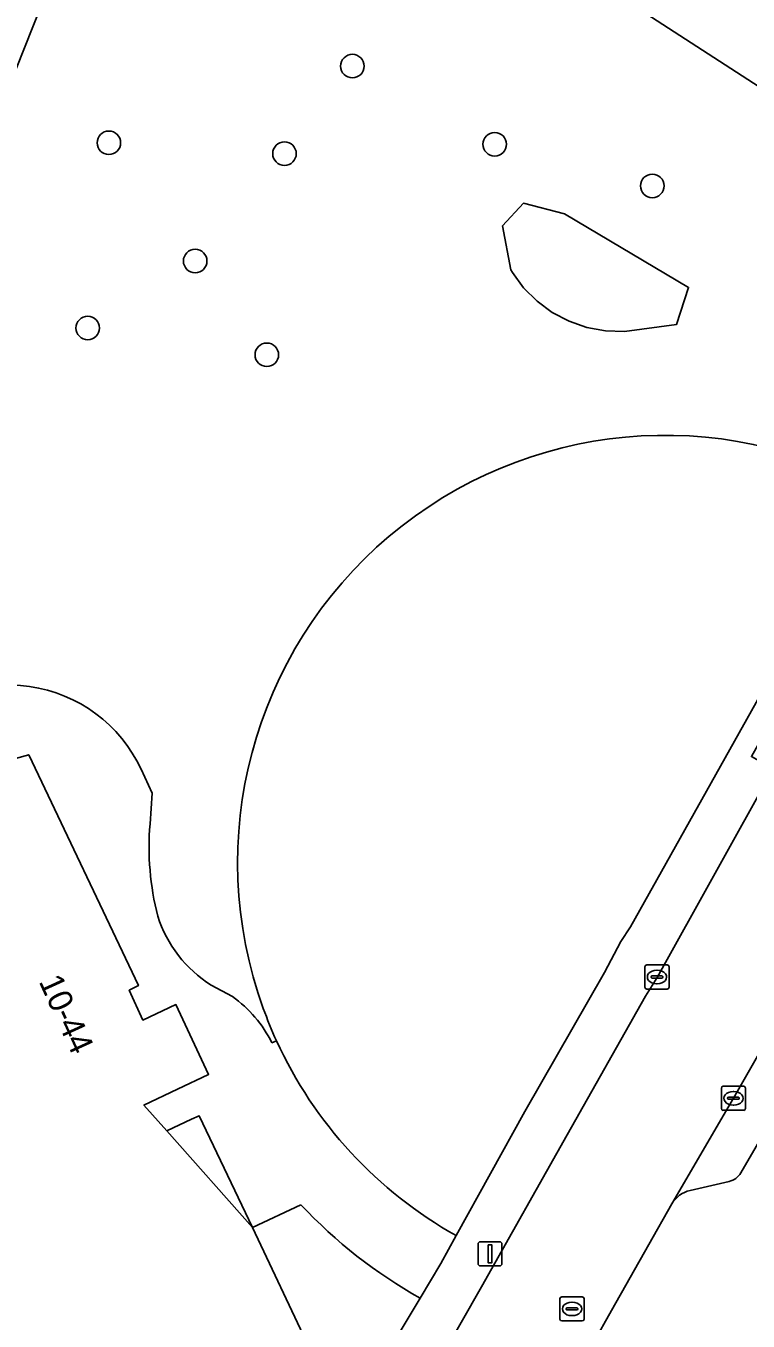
# Model space of a CAD drawing. Extents: x 159039 to 160102, y 381214 to 382524.
# Drawn here: x 159155.6 to 159185.6, y 381504.4 to 381558.2 of the extents above; entities that cross this region are included whole.
import ezdxf

# ---------------------------------------------------------------- set-up
doc = ezdxf.new("R2010")
doc.units = 0
for name, color, linetype in [('IMGEO_Boom', 7, 'Continuous'), ('IMGEO_Erf', 7, 'Continuous'), ('IMGEO_Groenvoorziening', 7, 'Continuous'), ('IMGEO_Kolk', 7, 'Continuous'), ('IMGEO_Lichtmast', 7, 'Continuous'), ('IMGEO_Pand', 7, 'Continuous'), ('IMGEO_Pand_nummerreeks', 7, 'Continuous'), ('IMGEO_Pand_overbouw', 7, 'Continuous'), ('IMGEO_Parkeervlak_open', 7, 'Continuous'), ('IMGEO_Rijbaan_lokaal_open', 7, 'Continuous'), ('IMGEO_Rioolput', 7, 'Continuous'), ('IMGEO_Voetpad_gesloten', 7, 'Continuous'), ('IMGEO_Voetpad_open', 7, 'Continuous')]:
    doc.layers.add(name, color=color, linetype=linetype)

msp = doc.modelspace()

# ---------------------------------------------------------------- linework, layer by layer
at = {"layer": 'IMGEO_Boom'}
for centre in [(159169.139, 381556.534), (159159.027, 381553.349), (159175.05, 381553.286), (159166.319, 381552.897), (159181.596, 381551.557), (159162.611, 381548.437), (159158.149, 381545.655), (159165.585, 381544.543)]:
    msp.add_circle(centre, 0.489, dxfattribs=at)
at = {"layer": 'IMGEO_Erf'}
msp.add_lwpolyline([(159173.453, 381507.955), (159176.296, 381513.115), (159179.604, 381518.88), (159180.292, 381520.169), (159180.696, 381520.785), (159188.162, 381534.124)], dxfattribs=at)
for centre, radius, start, end in [((159182.126, 381523.448), 17.751, 60.4649, 199.9506), ((159181.798, 381523.28), 17.386, 199.8006, 204.5674), ((159182.077, 381523.4), 17.69, 204.5429, 240.8212)]:
    msp.add_arc(centre, radius, start, end, dxfattribs=at)
at = {"layer": 'IMGEO_Groenvoorziening'}
for points in [[(159158.057, 381563.692), (159161.808, 381573.142), (159161.508, 381573.461), (159160.293, 381571.457), (159154.085, 381561.22), (159151.173, 381556.012), (159148.566, 381551.33), (159146.166, 381545.626), (159145.339, 381543.436), (159140.045, 381530.62), (159140.868, 381529.336), (159136.478, 381523.278), (159130.325, 381507.666), (159131.192, 381507.27), (159125.637, 381493.475), (159122.953, 381486.796), (159119.27, 381477.62), (159113.09, 381463.075), (159114.042, 381461.53), (159112.591, 381458.378), (159111.373, 381458.253), (159110.752, 381456.84), (159114.684, 381454.43)], [(159182.596, 381545.796), (159183.105, 381547.338), (159177.943, 381550.401), (159176.249, 381550.834), (159175.369, 381549.898), (159175.72, 381548.077), (159175.788, 381547.964), (159176.252, 381547.327), (159176.807, 381546.768), (159177.44, 381546.3), (159178.138, 381545.933), (159178.882, 381545.676), (159179.657, 381545.535), (159180.445, 381545.513)], [(159176.807, 381546.768), (159176.252, 381547.327), (159175.788, 381547.964), (159175.72, 381548.077), (159175.369, 381549.898), (159176.249, 381550.834), (159177.943, 381550.401), (159183.105, 381547.338), (159182.596, 381545.796), (159180.445, 381545.513), (159179.657, 381545.535), (159178.882, 381545.676), (159178.138, 381545.933), (159177.44, 381546.3)]]:
    msp.add_lwpolyline(points, close=True, dxfattribs=at)
for points in [[(159161.808, 381573.142), (159158.057, 381563.692), (159114.684, 381454.43), (159135.156, 381441.882)], [(159190.876, 381538.892), (159196.616, 381548.975), (159187.447, 381554.752), (159174.078, 381563.426), (159170.192, 381566.118)], [(159160.362, 381527.332), (159160.828, 381526.333), (159160.778, 381525.693), (159160.735, 381525.054)], [(159163.28, 381518.359), (159164.161, 381517.882)], [(159165.798, 381515.968), (159165.986, 381516.052)], [(159167, 381509.238), (159164.998, 381508.293), (159167.335, 381503.341), (159162.596, 381500), (159160.539, 381498.55), (159160.457, 381498.721), (159159.843, 381500), (159159.098, 381501.553), (159156.827, 381500.943), (159153.317, 381500)], [(159155.446, 381476.063), (159157.2, 381479.172), (159168.747, 381500), (159171.954, 381505.356)]]:
    msp.add_lwpolyline(points, dxfattribs=at)
for centre, radius, start, end in [((159182.126, 381523.448), 17.751, 60.4649, 199.9506), ((159154.882, 381524.776), 6.047, 25.0035, 138.8275), ((159172.244, 381524.098), 11.549, 175.2532, 194.3758), ((159166.045, 381522.795), 5.227, 197.412, 238.0695), ((159161.022, 381513.541), 5.357, 26.9441, 54.1352), ((159181.798, 381523.28), 17.386, 199.8006, 204.5674), ((159182.126, 381523.438), 20.747, 223.1931, 240.6418)]:
    msp.add_arc(centre, radius, start, end, dxfattribs=at)
at = {"layer": 'IMGEO_Kolk'}
for p, q in [((159181.289, 381518.27), (159181.289, 381519.122)), ((159181.364, 381519.196), (159182.216, 381519.196)), ((159181.777, 381518.976), (159181.802, 381518.976)), ((159182.29, 381519.122), (159182.29, 381518.27)), ((159181.548, 381518.69), (159181.548, 381518.702)), ((159181.986, 381518.653), (159181.588, 381518.653)), ((159181.591, 381518.739), (159181.989, 381518.739)), ((159182.032, 381518.702), (159182.032, 381518.69)), ((159182.216, 381518.196), (159181.364, 381518.196)), ((159181.8, 381518.416), (159181.775, 381518.416)), ((159184.54, 381514.159), (159185.392, 381514.159)), ((159184.465, 381513.233), (159184.465, 381514.085)), ((159184.724, 381513.653), (159184.724, 381513.665)), ((159185.162, 381513.616), (159184.764, 381513.616)), ((159184.767, 381513.702), (159185.165, 381513.702)), ((159184.953, 381513.939), (159184.978, 381513.939)), ((159185.208, 381513.665), (159185.208, 381513.653)), ((159185.466, 381514.085), (159185.466, 381513.233)), ((159185.392, 381513.159), (159184.54, 381513.159)), ((159184.976, 381513.379), (159184.951, 381513.379))]:
    msp.add_line(p, q, dxfattribs=at)
for points in [[(159181.289, 381518.27), (159181.289, 381519.122)], [(159181.364, 381519.196), (159182.216, 381519.196)], [(159182.29, 381519.122), (159182.29, 381518.27)], [(159182.216, 381518.196), (159181.364, 381518.196)], [(159184.54, 381514.159), (159185.392, 381514.159)], [(159184.465, 381513.233), (159184.465, 381514.085)], [(159185.466, 381514.085), (159185.466, 381513.233)], [(159185.392, 381513.159), (159184.54, 381513.159)]]:
    msp.add_lwpolyline(points, dxfattribs=at)
for centre, radius, start, end in [((159181.366, 381519.12), 0.0765, 91.552, 178.448), ((159181.366, 381519.12), 0.0765, 91.552, 178.448), ((159182.214, 381519.12), 0.0765, 1.552, 88.448), ((159182.214, 381519.12), 0.0765, 1.552, 88.448), ((159181.588, 381518.699), 0.0403, 85.8775, 175.7526), ((159181.585, 381518.689), 0.0366, 178.938, 274.7102), ((159181.989, 381518.696), 0.043, 264.8664, 352.4533), ((159181.993, 381518.701), 0.0386, 1.7309, 96.639), ((159181.366, 381518.272), 0.0765, 181.552, 268.448), ((159181.366, 381518.272), 0.0765, 181.552, 268.448), ((159182.214, 381518.272), 0.0765, 271.552, 358.448), ((159182.214, 381518.272), 0.0765, 271.552, 358.448), ((159184.542, 381514.083), 0.0765, 91.552, 178.448), ((159184.542, 381514.083), 0.0765, 91.552, 178.448), ((159185.39, 381514.083), 0.0765, 1.552, 88.448), ((159185.39, 381514.083), 0.0765, 1.552, 88.448), ((159184.764, 381513.662), 0.0403, 85.8775, 175.7526), ((159184.761, 381513.652), 0.0366, 178.938, 274.7102), ((159185.165, 381513.659), 0.043, 264.8664, 352.4533), ((159185.169, 381513.664), 0.0386, 1.7309, 96.639), ((159184.542, 381513.235), 0.0765, 181.552, 268.448), ((159184.542, 381513.235), 0.0765, 181.552, 268.448), ((159185.39, 381513.235), 0.0765, 271.552, 358.448), ((159185.39, 381513.235), 0.0765, 271.552, 358.448)]:
    msp.add_arc(centre, radius, start, end, dxfattribs=at)
for centre, major_axis, ratio, start_param, end_param in [((159181.776, 381518.696), (-0.387, 0.002), 0.722429, 4.712389, 7.853982), ((159181.801, 381518.696), (-0.39, 0.002), 0.717154, 1.570796, 4.712389), ((159184.952, 381513.659), (-0.387, 0.002), 0.722429, 4.712389, 7.853982), ((159184.977, 381513.659), (-0.39, 0.002), 0.717154, 1.570796, 4.712389)]:
    msp.add_ellipse(centre, major_axis=major_axis, ratio=ratio, start_param=start_param, end_param=end_param, dxfattribs=at)
at = {"layer": 'IMGEO_Lichtmast'}
for p, q in [((159174.459, 381507.698), (159175.249, 381507.698)), ((159175.249, 381507.698), (159174.459, 381507.698)), ((159174.359, 381506.798), (159174.359, 381507.598)), ((159174.359, 381507.598), (159174.359, 381506.798)), ((159175.349, 381507.598), (159175.349, 381506.798)), ((159175.349, 381506.798), (159175.349, 381507.598)), ((159175.249, 381506.698), (159174.459, 381506.698)), ((159174.459, 381506.698), (159175.249, 381506.698))]:
    msp.add_line(p, q, dxfattribs=at)
msp.add_lwpolyline([(159174.779, 381507.573), (159174.929, 381507.573), (159174.929, 381506.823), (159174.779, 381506.823), (159174.779, 381507.573)], dxfattribs=at)
for centre, start, end in [((159174.459, 381507.598), 90, 180), ((159174.459, 381507.598), 90, 180), ((159175.249, 381507.598), 0, 90), ((159175.249, 381507.598), 360, 90), ((159174.459, 381506.798), 180, 270), ((159174.459, 381506.798), 180, 270), ((159175.249, 381506.798), 270, 0), ((159175.249, 381506.798), 270, 0)]:
    msp.add_arc(centre, 0.1, start, end, dxfattribs=at)
at = {"layer": 'IMGEO_Pand'}
msp.add_lwpolyline([(159153.317, 381500), (159156.827, 381500.943), (159159.098, 381501.553), (159159.843, 381500), (159160.457, 381498.721), (159160.539, 381498.55), (159162.596, 381500), (159167.335, 381503.341), (159164.998, 381508.293), (159161.431, 381512.312), (159160.484, 381513.379), (159161.874, 381514.04), (159163.165, 381514.654), (159161.814, 381517.55), (159160.44, 381516.91), (159159.875, 381518.147), (159160.252, 381518.344), (159155.698, 381527.931), (159147.68, 381525.728)], dxfattribs=at)
at = {"layer": 'IMGEO_Pand_overbouw'}
msp.add_lwpolyline([(159161.431, 381512.312), (159164.998, 381508.293), (159162.77, 381512.936), (159162.461, 381512.792)], close=True, dxfattribs=at)
at = {"layer": 'IMGEO_Parkeervlak_open'}
for points in [[(159210.549, 381559.319), (159207.32, 381553.722), (159202.327, 381544.533), (159197.222, 381535.339), (159195.889, 381532.938), (159193.161, 381528.024), (159184.97, 381513.668), (159182.408, 381509.281)], [(159185.268, 381510.556), (159186.552, 381512.755), (159194.753, 381527.128), (159203.917, 381543.633), (159208.914, 381552.829), (159212.162, 381558.46), (159212.41, 381558.977)], [(159183.165, 381509.829), (159184.789, 381510.203)]]:
    msp.add_lwpolyline(points, dxfattribs=at)
for centre, radius, start, end in [((159184.62, 381510.934), 0.75, 283.0289, 329.748), ((159183.433, 381508.662), 1.198, 102.9364, 148.8659)]:
    msp.add_arc(centre, radius, start, end, dxfattribs=at)
at = {"layer": 'IMGEO_Rijbaan_lokaal_open'}
msp.add_lwpolyline([(159178.373, 381502.132), (159179.901, 381504.839), (159181.449, 381507.583), (159182.408, 381509.281), (159184.97, 381513.668), (159193.161, 381528.024), (159195.889, 381532.938), (159191.214, 381535.521), (159190.114, 381533.578), (159189.893, 381533.157), (159186.615, 381527.344), (159181.803, 381518.679), (159181.307, 381517.904), (159178.059, 381512.136), (159174.495, 381505.831), (159171.178, 381500)], dxfattribs=at)
at = {"layer": 'IMGEO_Rioolput'}
for p, q in [((159177.76, 381504.486), (159177.76, 381505.338)), ((159177.835, 381505.412), (159178.687, 381505.412)), ((159178.248, 381505.192), (159178.273, 381505.192)), ((159178.761, 381505.338), (159178.761, 381504.486)), ((159178.019, 381504.906), (159178.019, 381504.918)), ((159178.457, 381504.869), (159178.059, 381504.869)), ((159178.062, 381504.955), (159178.46, 381504.955)), ((159178.271, 381504.632), (159178.246, 381504.632)), ((159178.503, 381504.918), (159178.503, 381504.906)), ((159178.687, 381504.412), (159177.835, 381504.412))]:
    msp.add_line(p, q, dxfattribs=at)
for points in [[(159177.76, 381504.486), (159177.76, 381505.338)], [(159177.835, 381505.412), (159178.687, 381505.412)], [(159178.761, 381505.338), (159178.761, 381504.486)], [(159178.687, 381504.412), (159177.835, 381504.412)]]:
    msp.add_lwpolyline(points, dxfattribs=at)
for centre, radius, start, end in [((159177.837, 381505.336), 0.0765, 91.552, 178.448), ((159177.837, 381505.336), 0.0765, 91.552, 178.448), ((159178.685, 381505.336), 0.0765, 1.552, 88.448), ((159178.685, 381505.336), 0.0765, 1.552, 88.448), ((159177.837, 381504.488), 0.0765, 181.552, 268.448), ((159177.837, 381504.488), 0.0765, 181.552, 268.448), ((159178.059, 381504.915), 0.0403, 85.8775, 175.7526), ((159178.056, 381504.905), 0.0366, 178.938, 274.7102), ((159178.46, 381504.912), 0.043, 264.8664, 352.4533), ((159178.464, 381504.917), 0.0386, 1.7309, 96.639), ((159178.685, 381504.488), 0.0765, 271.552, 358.448), ((159178.685, 381504.488), 0.0765, 271.552, 358.448)]:
    msp.add_arc(centre, radius, start, end, dxfattribs=at)
for centre, major_axis, ratio, start_param, end_param in [((159178.247, 381504.912), (-0.387, 0.002), 0.722429, 4.712389, 7.853982), ((159178.272, 381504.912), (-0.39, 0.002), 0.717154, 1.570796, 4.712389)]:
    msp.add_ellipse(centre, major_axis=major_axis, ratio=ratio, start_param=start_param, end_param=end_param, dxfattribs=at)
at = {"layer": 'IMGEO_Voetpad_gesloten'}
msp.add_lwpolyline([(159170.192, 381566.118), (159174.078, 381563.426), (159187.447, 381554.752), (159196.616, 381548.975), (159197.939, 381551.409), (159188.941, 381557.082), (159178.197, 381564.042), (159173.956, 381566.79), (159169.761, 381569.755)], dxfattribs=at)
at = {"layer": 'IMGEO_Voetpad_open'}
for points in [[(159202.211, 381559.115), (159197.939, 381551.409), (159196.616, 381548.975), (159190.876, 381538.892), (159188.162, 381534.124), (159180.696, 381520.785), (159180.292, 381520.169), (159179.604, 381518.88), (159176.296, 381513.115), (159173.453, 381507.955), (159172.813, 381506.792), (159171.954, 381505.356), (159168.747, 381500)], [(159212.41, 381558.977), (159212.162, 381558.46), (159208.914, 381552.829), (159203.917, 381543.633), (159194.753, 381527.128), (159186.552, 381512.755), (159185.268, 381510.556)], [(159142.37, 381448.941), (159146.11, 381455.538), (159151.125, 381464.42), (159154.371, 381470.177), (159154.48, 381470.371), (159155.72, 381472.568), (159158.808, 381478.041), (159162.975, 381485.583), (159169.891, 381497.722), (159171.178, 381500), (159174.495, 381505.831), (159178.059, 381512.136), (159181.307, 381517.904), (159181.803, 381518.679), (159186.615, 381527.344), (159185.709, 381527.855), (159188.987, 381533.668), (159189.893, 381533.157), (159190.114, 381533.578), (159191.214, 381535.521), (159191.522, 381536.074)], [(159150.33, 381528.757), (159147.68, 381525.728), (159155.698, 381527.931), (159160.252, 381518.344), (159159.875, 381518.147), (159160.44, 381516.91), (159161.814, 381517.55), (159163.165, 381514.654), (159161.874, 381514.04), (159160.484, 381513.379), (159161.431, 381512.312), (159164.998, 381508.293), (159167, 381509.238)], [(159160.735, 381525.054), (159160.778, 381525.693), (159160.828, 381526.333), (159160.362, 381527.332)], [(159164.161, 381517.882), (159163.28, 381518.359)], [(159165.986, 381516.052), (159165.798, 381515.968)], [(159184.789, 381510.203), (159183.165, 381509.829)], [(159182.408, 381509.281), (159181.449, 381507.583), (159179.901, 381504.839), (159178.373, 381502.132), (159177.471, 381500.513), (159177.339, 381500.28), (159177.182, 381500), (159176.43, 381498.578), (159175.862, 381497.614)], [(159171.954, 381505.356), (159172.813, 381506.792), (159173.453, 381507.955)]]:
    msp.add_lwpolyline(points, dxfattribs=at)
for centre, radius, start, end in [((159154.882, 381524.776), 6.047, 25.0035, 138.8275), ((159172.244, 381524.098), 11.549, 175.2532, 194.3758), ((159166.045, 381522.795), 5.227, 197.412, 238.0695), ((159161.022, 381513.541), 5.357, 26.9441, 54.1352), ((159182.077, 381523.4), 17.69, 204.5429, 240.8212), ((159184.62, 381510.934), 0.75, 283.0289, 329.748), ((159183.433, 381508.662), 1.198, 102.9364, 148.8659), ((159182.126, 381523.438), 20.747, 223.1931, 240.6418)]:
    msp.add_arc(centre, radius, start, end, dxfattribs=at)

# ---------------------------------------------------------------- texts
at = {"layer": 'IMGEO_Pand_nummerreeks'}
msp.add_text('10-44', height=1, rotation=294.5486, dxfattribs=at).set_placement((159156.1, 381518.518))

doc.saveas('drawing.dxf')
